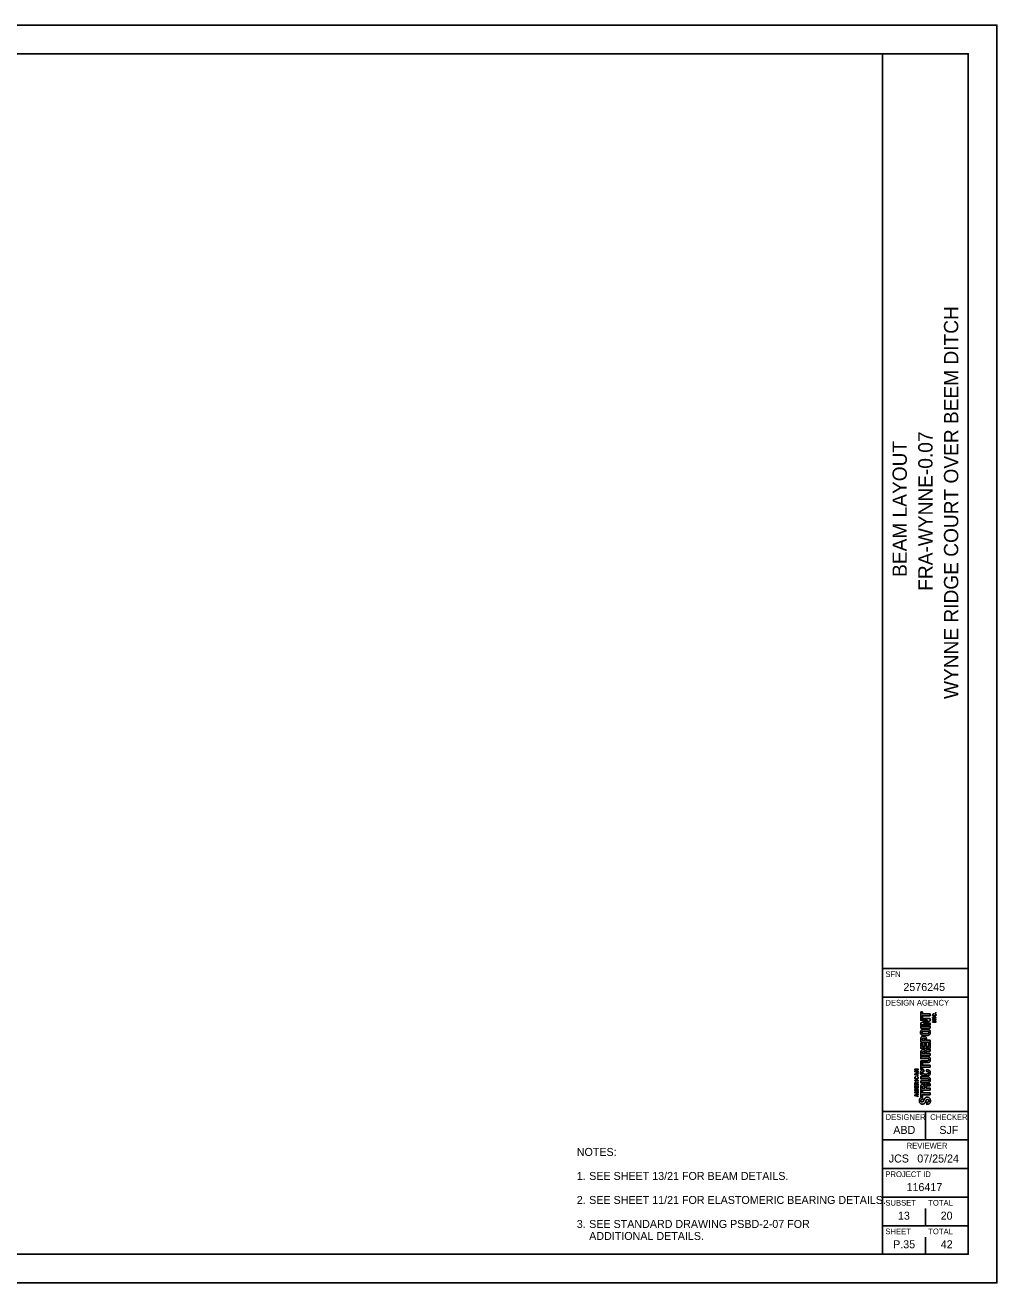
# Model space of a CAD drawing. Extents: x 0 to 34, y 0 to 22.
# Drawn here: x 17 to 34, y 0 to 22 of the extents above; entities that cross this region are included whole.
import ezdxf

# ---------------------------------------------------------------- set-up
doc = ezdxf.new("R2010")
doc.units = 0
for name, color, linetype in [('GE_X_Alignment', 7, 'Continuous'), ('PF_P_Grade_Line', 7, 'Continuous'), ('RW_X_CL', 7, 'Continuous'), ('RW_X_CL_20', 7, 'Continuous')]:
    doc.layers.add(name, color=color, linetype=linetype)

msp = doc.modelspace()

# ---------------------------------------------------------------- linework, layer by layer
at = {"layer": 'GE_X_Alignment'}
for p, q in [((32.75, 4), (32.75, 4)), ((32.75, 4), (32.75, 4)), ((32.75, 1), (32.75, 1.3)), ((32.375, 0.675), (32.375, 0.675)), ((32.75, 0.5), (32.75, 0.8))]:
    msp.add_line(p, q, dxfattribs=at)
for points in [[(32.67, 4.739), (32.697, 4.739), (32.697, 4.704), (32.833, 4.704), (32.833, 4.671), (32.697, 4.671), (32.697, 4.635), (32.67, 4.635), (32.67, 4.739)], [(32.67, 4.551), (32.781, 4.591), (32.781, 4.592), (32.67, 4.592), (32.67, 4.622), (32.833, 4.622), (32.833, 4.584), (32.719, 4.544), (32.719, 4.544), (32.833, 4.544), (32.833, 4.513), (32.67, 4.513), (32.67, 4.551)], [(32.875, 4.596), (32.875, 4.605), (32.925, 4.634), (32.925, 4.634), (32.875, 4.634), (32.875, 4.639), (32.935, 4.639), (32.935, 4.634), (32.88, 4.602), (32.88, 4.601), (32.935, 4.601), (32.935, 4.596), (32.875, 4.596)], [(32.935, 4.718), (32.927, 4.718), (32.927, 4.725), (32.935, 4.725), (32.935, 4.718)], [(32.833, 4.457), (32.67, 4.457), (32.67, 4.49), (32.833, 4.49), (32.833, 4.457)], [(32.875, 4.561), (32.875, 4.567), (32.935, 4.567), (32.935, 4.561), (32.875, 4.561)], [(32.833, 4.212), (32.67, 4.212), (32.67, 4.269)], [(32.67, 4.194), (32.697, 4.194), (32.697, 4.135), (32.735, 4.135), (32.735, 4.19), (32.762, 4.19), (32.762, 4.135), (32.806, 4.135), (32.806, 4.196), (32.833, 4.196), (32.833, 4.103), (32.67, 4.103), (32.67, 4.194)], [(32.694, 4.244), (32.743, 4.244), (32.743, 4.259)], [(32.694, 4.258), (32.694, 4.244)], [(32.768, 4.262), (32.768, 4.244), (32.833, 4.244), (32.833, 4.212)], [(32.833, 3.976), (32.67, 3.976), (32.67, 4.037)], [(32.694, 4.025), (32.694, 4.009)], [(32.694, 4.009), (32.741, 4.009), (32.741, 4.023)], [(32.752, 4.054), (32.752, 4.054)], [(32.764, 4.027), (32.764, 4.009), (32.833, 4.009), (32.833, 3.976)], [(32.816, 4.048), (32.784, 4.047)], [(32.832, 4.087), (32.833, 4.087), (32.833, 4.052)], [(32.67, 3.841), (32.697, 3.841), (32.697, 3.805), (32.833, 3.805), (32.833, 3.773), (32.697, 3.773), (32.697, 3.737), (32.67, 3.737), (32.67, 3.841)], [(32.565, 3.694), (32.565, 3.703), (32.615, 3.731), (32.615, 3.731), (32.565, 3.731), (32.565, 3.737), (32.625, 3.737), (32.625, 3.731), (32.569, 3.699), (32.569, 3.699), (32.625, 3.699), (32.625, 3.694), (32.565, 3.694)], [(32.625, 3.625), (32.565, 3.644), (32.565, 3.652), (32.625, 3.671), (32.625, 3.665), (32.605, 3.659), (32.605, 3.637), (32.625, 3.631), (32.625, 3.625)], [(32.565, 3.534), (32.565, 3.539), (32.625, 3.539), (32.625, 3.534), (32.565, 3.534)], [(32.601, 3.638), (32.601, 3.658), (32.569, 3.648), (32.569, 3.648), (32.601, 3.638)], [(32.596, 3.492), (32.625, 3.506), (32.625, 3.5), (32.597, 3.487), (32.597, 3.471), (32.625, 3.471), (32.625, 3.466), (32.565, 3.466), (32.565, 3.486)], [(32.625, 3.407), (32.565, 3.407), (32.565, 3.441), (32.569, 3.441), (32.569, 3.413), (32.591, 3.413), (32.591, 3.433), (32.596, 3.433), (32.596, 3.413), (32.62, 3.413), (32.62, 3.443), (32.625, 3.443), (32.625, 3.407)], [(32.625, 3.326), (32.565, 3.326), (32.565, 3.336), (32.615, 3.352), (32.615, 3.353), (32.565, 3.369), (32.565, 3.379), (32.625, 3.379), (32.625, 3.373), (32.569, 3.373), (32.569, 3.373), (32.625, 3.355), (32.625, 3.35), (32.569, 3.332), (32.569, 3.332), (32.625, 3.332), (32.625, 3.326)], [(32.625, 3.258), (32.565, 3.277), (32.565, 3.285), (32.625, 3.304), (32.625, 3.298), (32.605, 3.292), (32.605, 3.269), (32.625, 3.263), (32.625, 3.258)], [(32.569, 3.471), (32.593, 3.471), (32.593, 3.486)], [(32.569, 3.486), (32.569, 3.471)], [(32.833, 3.373), (32.67, 3.373), (32.67, 3.434)], [(32.67, 3.36), (32.697, 3.36), (32.697, 3.324), (32.833, 3.324), (32.833, 3.291), (32.697, 3.291), (32.697, 3.256), (32.67, 3.256), (32.67, 3.36)], [(32.694, 3.422), (32.694, 3.406)], [(32.694, 3.406), (32.741, 3.406), (32.741, 3.42)], [(32.752, 3.451), (32.752, 3.451)], [(32.764, 3.424), (32.764, 3.406), (32.833, 3.406), (32.833, 3.373)], [(32.816, 3.444), (32.784, 3.444)], [(32.832, 3.484), (32.833, 3.484), (32.833, 3.449)], [(32.601, 3.271), (32.601, 3.291), (32.569, 3.281), (32.569, 3.281), (32.601, 3.271)]]:
    msp.add_lwpolyline(points, dxfattribs=at)
for points in [[(32.893, 4.701), (32.889, 4.699), (32.885, 4.697), (32.883, 4.695), (32.88, 4.693), (32.879, 4.69), (32.879, 4.686), (32.879, 4.683), (32.88, 4.681), (32.881, 4.678), (32.882, 4.676), (32.884, 4.675), (32.887, 4.673), (32.889, 4.672), (32.892, 4.671), (32.895, 4.67), (32.898, 4.669), (32.902, 4.669), (32.905, 4.669), (32.909, 4.669), (32.912, 4.669), (32.915, 4.67), (32.919, 4.671), (32.921, 4.672), (32.924, 4.673), (32.926, 4.675), (32.928, 4.676), (32.929, 4.679), (32.931, 4.681), (32.931, 4.684), (32.931, 4.687), (32.931, 4.689), (32.931, 4.691), (32.93, 4.693), (32.929, 4.694), (32.928, 4.696), (32.927, 4.697), (32.926, 4.698), (32.924, 4.699), (32.922, 4.7), (32.921, 4.7), (32.919, 4.701), (32.917, 4.702), (32.917, 4.702), (32.918, 4.707), (32.918, 4.707), (32.92, 4.706), (32.923, 4.705), (32.925, 4.704), (32.927, 4.703), (32.929, 4.702), (32.931, 4.7), (32.932, 4.699), (32.934, 4.697), (32.934, 4.695), (32.935, 4.692), (32.936, 4.69), (32.936, 4.687), (32.936, 4.683), (32.935, 4.68), (32.934, 4.677), (32.932, 4.674), (32.93, 4.672), (32.927, 4.67), (32.925, 4.668), (32.921, 4.666), (32.918, 4.665), (32.914, 4.664), (32.91, 4.664), (32.905, 4.664), (32.901, 4.664), (32.896, 4.664), (32.893, 4.665), (32.889, 4.666), (32.886, 4.668), (32.883, 4.67), (32.88, 4.672), (32.878, 4.674), (32.877, 4.677), (32.875, 4.68), (32.875, 4.683), (32.875, 4.687), (32.875, 4.689), (32.875, 4.692), (32.876, 4.694), (32.877, 4.696), (32.878, 4.698), (32.88, 4.699), (32.881, 4.701), (32.883, 4.702), (32.885, 4.703), (32.887, 4.704), (32.889, 4.705), (32.892, 4.706), (32.892, 4.706), (32.893, 4.701), (32.893, 4.701)], [(32.751, 4.326), (32.739, 4.326), (32.727, 4.326), (32.717, 4.328), (32.706, 4.329), (32.697, 4.331), (32.69, 4.335), (32.682, 4.339), (32.677, 4.345), (32.672, 4.352), (32.668, 4.359), (32.666, 4.369), (32.666, 4.382), (32.666, 4.394), (32.668, 4.404), (32.672, 4.411), (32.677, 4.418), (32.682, 4.424), (32.69, 4.428), (32.697, 4.432), (32.706, 4.434), (32.717, 4.436), (32.727, 4.437), (32.739, 4.437), (32.751, 4.437), (32.758, 4.437), (32.764, 4.437), (32.771, 4.437)], [(32.751, 4.359), (32.762, 4.359), (32.771, 4.359), (32.779, 4.359), (32.787, 4.36), (32.793, 4.361), (32.798, 4.363), (32.803, 4.364), (32.806, 4.367), (32.808, 4.37), (32.81, 4.373), (32.812, 4.377), (32.812, 4.382), (32.812, 4.386), (32.81, 4.39), (32.808, 4.393), (32.806, 4.396), (32.803, 4.399), (32.798, 4.4), (32.793, 4.402), (32.787, 4.403), (32.779, 4.404), (32.771, 4.404), (32.762, 4.404), (32.751, 4.404), (32.74, 4.404), (32.731, 4.404), (32.723, 4.404), (32.716, 4.403), (32.709, 4.402), (32.704, 4.4), (32.7, 4.399), (32.696, 4.396), (32.694, 4.393), (32.692, 4.39), (32.691, 4.386), (32.691, 4.382), (32.691, 4.377), (32.692, 4.373), (32.694, 4.37), (32.696, 4.367), (32.7, 4.364), (32.704, 4.363), (32.709, 4.361), (32.716, 4.36), (32.723, 4.359), (32.731, 4.359), (32.74, 4.359), (32.751, 4.359)], [(32.771, 4.437), (32.776, 4.436), (32.781, 4.436), (32.785, 4.436), (32.796, 4.434), (32.805, 4.432), (32.812, 4.428), (32.82, 4.424), (32.825, 4.418), (32.83, 4.411), (32.834, 4.404), (32.836, 4.394), (32.836, 4.382), (32.836, 4.369), (32.834, 4.359), (32.83, 4.352), (32.825, 4.345), (32.82, 4.339), (32.812, 4.335), (32.805, 4.331), (32.796, 4.329), (32.785, 4.328), (32.775, 4.326), (32.763, 4.326), (32.751, 4.326)], [(32.67, 4.269), (32.67, 4.277), (32.671, 4.284), (32.674, 4.29), (32.677, 4.296), (32.68, 4.3), (32.685, 4.304), (32.689, 4.307), (32.695, 4.31), (32.701, 4.312), (32.706, 4.313), (32.712, 4.314), (32.719, 4.314), (32.727, 4.314), (32.734, 4.313), (32.741, 4.31), (32.747, 4.308), (32.752, 4.304), (32.756, 4.3), (32.76, 4.295), (32.763, 4.29), (32.765, 4.283), (32.767, 4.277), (32.768, 4.27), (32.768, 4.262)], [(32.743, 4.259), (32.743, 4.266), (32.741, 4.271), (32.737, 4.275), (32.733, 4.279), (32.727, 4.281), (32.719, 4.281), (32.711, 4.281), (32.705, 4.279), (32.7, 4.276), (32.696, 4.272), (32.694, 4.266), (32.694, 4.258)], [(32.67, 4.037), (32.67, 4.051), (32.673, 4.062), (32.68, 4.069), (32.687, 4.077), (32.698, 4.081), (32.712, 4.081), (32.723, 4.081), (32.732, 4.079), (32.739, 4.074), (32.745, 4.07), (32.75, 4.063), (32.752, 4.054)], [(32.741, 4.023), (32.741, 4.031), (32.739, 4.037), (32.735, 4.042), (32.732, 4.046), (32.725, 4.048), (32.717, 4.048), (32.702, 4.048), (32.694, 4.04), (32.694, 4.025)], [(32.752, 4.054), (32.753, 4.059), (32.755, 4.064), (32.757, 4.067), (32.759, 4.071), (32.762, 4.073), (32.766, 4.075), (32.769, 4.077), (32.774, 4.078), (32.78, 4.079), (32.786, 4.08), (32.794, 4.08), (32.802, 4.08), (32.811, 4.08), (32.818, 4.081), (32.822, 4.082), (32.827, 4.082), (32.83, 4.084), (32.832, 4.087)], [(32.784, 4.047), (32.778, 4.046), (32.773, 4.045), (32.769, 4.042), (32.766, 4.039), (32.764, 4.034), (32.764, 4.027)], [(32.833, 4.052), (32.831, 4.05), (32.828, 4.049), (32.825, 4.049), (32.822, 4.048), (32.819, 4.048), (32.816, 4.048)], [(32.67, 3.885), (32.67, 3.885), (32.783, 3.885), (32.783, 3.885), (32.787, 3.885), (32.791, 3.885), (32.795, 3.886), (32.798, 3.887), (32.801, 3.888), (32.803, 3.889), (32.806, 3.89), (32.808, 3.892), (32.809, 3.895), (32.811, 3.897), (32.812, 3.901), (32.812, 3.904), (32.812, 3.908), (32.811, 3.911), (32.809, 3.914), (32.808, 3.917), (32.806, 3.918), (32.803, 3.92), (32.801, 3.921), (32.798, 3.922), (32.795, 3.923), (32.791, 3.923), (32.787, 3.924), (32.783, 3.924), (32.783, 3.924), (32.67, 3.924), (32.67, 3.924), (32.67, 3.924), (32.67, 3.957), (32.67, 3.957), (32.67, 3.957), (32.783, 3.957), (32.783, 3.957), (32.794, 3.957), (32.802, 3.955), (32.809, 3.952), (32.816, 3.949), (32.821, 3.945), (32.825, 3.941), (32.829, 3.936), (32.832, 3.93), (32.834, 3.924), (32.835, 3.918), (32.836, 3.911), (32.836, 3.904), (32.836, 3.898), (32.835, 3.891), (32.834, 3.885), (32.833, 3.879), (32.83, 3.873), (32.826, 3.868), (32.822, 3.863), (32.817, 3.86), (32.81, 3.857), (32.803, 3.854), (32.794, 3.852), (32.783, 3.852), (32.783, 3.852), (32.67, 3.852), (32.67, 3.852), (32.67, 3.852), (32.67, 3.885), (32.67, 3.885)], [(32.582, 3.601), (32.578, 3.6), (32.575, 3.598), (32.572, 3.595), (32.57, 3.593), (32.569, 3.59), (32.569, 3.586), (32.569, 3.583), (32.569, 3.581), (32.571, 3.579), (32.572, 3.577), (32.574, 3.575), (32.576, 3.574), (32.579, 3.572), (32.581, 3.571), (32.585, 3.57), (32.588, 3.57), (32.591, 3.569), (32.595, 3.569), (32.598, 3.569), (32.602, 3.57), (32.605, 3.57), (32.608, 3.571), (32.611, 3.572), (32.613, 3.574), (32.616, 3.575), (32.618, 3.577), (32.619, 3.579), (32.62, 3.581), (32.621, 3.584), (32.621, 3.587), (32.621, 3.589), (32.62, 3.591), (32.62, 3.593), (32.619, 3.595), (32.618, 3.596), (32.617, 3.597), (32.615, 3.598), (32.614, 3.599), (32.612, 3.6), (32.61, 3.601), (32.608, 3.602), (32.606, 3.602), (32.606, 3.602), (32.607, 3.607), (32.607, 3.607), (32.61, 3.607), (32.612, 3.606), (32.615, 3.605), (32.617, 3.604), (32.619, 3.602), (32.62, 3.601), (32.622, 3.599), (32.623, 3.597), (32.624, 3.595), (32.625, 3.593), (32.625, 3.59), (32.625, 3.587), (32.625, 3.583), (32.625, 3.58), (32.623, 3.577), (32.622, 3.574), (32.62, 3.572), (32.617, 3.57), (32.614, 3.568), (32.611, 3.567), (32.607, 3.566), (32.604, 3.565), (32.599, 3.564), (32.595, 3.564), (32.59, 3.564), (32.586, 3.565), (32.582, 3.566), (32.579, 3.567), (32.575, 3.568), (32.573, 3.57), (32.57, 3.572), (32.568, 3.574), (32.566, 3.577), (32.565, 3.58), (32.564, 3.583), (32.564, 3.587), (32.564, 3.59), (32.565, 3.592), (32.566, 3.594), (32.566, 3.596), (32.568, 3.598), (32.569, 3.599), (32.571, 3.601), (32.572, 3.602), (32.575, 3.603), (32.577, 3.604), (32.579, 3.605), (32.581, 3.606), (32.581, 3.606), (32.582, 3.601), (32.582, 3.601)], [(32.725, 3.693), (32.713, 3.693), (32.704, 3.692), (32.699, 3.689), (32.693, 3.686), (32.691, 3.681), (32.691, 3.674), (32.691, 3.67), (32.692, 3.666), (32.694, 3.663), (32.696, 3.661), (32.7, 3.659), (32.705, 3.657), (32.71, 3.656), (32.716, 3.655), (32.724, 3.654), (32.732, 3.653), (32.742, 3.653), (32.753, 3.653), (32.766, 3.653), (32.776, 3.653), (32.783, 3.654), (32.791, 3.655), (32.797, 3.656), (32.801, 3.658), (32.805, 3.66), (32.808, 3.662), (32.809, 3.665), (32.811, 3.668), (32.812, 3.671), (32.812, 3.674), (32.812, 3.677), (32.811, 3.68), (32.81, 3.682), (32.809, 3.685), (32.807, 3.687), (32.804, 3.689), (32.801, 3.691), (32.797, 3.692), (32.792, 3.693), (32.786, 3.694), (32.779, 3.695), (32.77, 3.695), (32.77, 3.695), (32.77, 3.728), (32.77, 3.728), (32.779, 3.728), (32.787, 3.727), (32.795, 3.726), (32.803, 3.724), (32.81, 3.722), (32.816, 3.718), (32.822, 3.714), (32.827, 3.709), (32.831, 3.702), (32.834, 3.696), (32.836, 3.687), (32.836, 3.676), (32.836, 3.663), (32.834, 3.654), (32.83, 3.646), (32.825, 3.639), (32.82, 3.633), (32.812, 3.629), (32.805, 3.626), (32.796, 3.623), (32.785, 3.622), (32.775, 3.621), (32.763, 3.62), (32.751, 3.62), (32.739, 3.62), (32.727, 3.621), (32.717, 3.622), (32.706, 3.623), (32.697, 3.626), (32.69, 3.629), (32.682, 3.633), (32.677, 3.639), (32.672, 3.646), (32.668, 3.654), (32.666, 3.663), (32.666, 3.676), (32.666, 3.688), (32.668, 3.697), (32.672, 3.704), (32.676, 3.71), (32.681, 3.715), (32.687, 3.719), (32.692, 3.722), (32.699, 3.724), (32.706, 3.725), (32.712, 3.726), (32.719, 3.726), (32.725, 3.726), (32.725, 3.726), (32.725, 3.693), (32.725, 3.693)], [(32.67, 3.532), (32.67, 3.532), (32.783, 3.532), (32.783, 3.532), (32.787, 3.532), (32.791, 3.533), (32.795, 3.533), (32.798, 3.534), (32.801, 3.535), (32.803, 3.536), (32.806, 3.538), (32.808, 3.54), (32.809, 3.542), (32.811, 3.545), (32.812, 3.548), (32.812, 3.552), (32.812, 3.556), (32.811, 3.559), (32.809, 3.561), (32.808, 3.564), (32.806, 3.566), (32.803, 3.567), (32.801, 3.569), (32.798, 3.57), (32.795, 3.57), (32.791, 3.571), (32.787, 3.571), (32.783, 3.571), (32.783, 3.571), (32.67, 3.571), (32.67, 3.571), (32.67, 3.571), (32.67, 3.604), (32.67, 3.604), (32.67, 3.604), (32.783, 3.604), (32.783, 3.604), (32.794, 3.604), (32.802, 3.602), (32.809, 3.6), (32.816, 3.597), (32.821, 3.593), (32.825, 3.588), (32.829, 3.583), (32.832, 3.577), (32.834, 3.571), (32.835, 3.565), (32.836, 3.558), (32.836, 3.552), (32.836, 3.545), (32.835, 3.539), (32.834, 3.532), (32.833, 3.526), (32.83, 3.521), (32.826, 3.516), (32.822, 3.511), (32.817, 3.507), (32.81, 3.504), (32.803, 3.501), (32.794, 3.5), (32.783, 3.5), (32.783, 3.5), (32.67, 3.5), (32.67, 3.5), (32.67, 3.5), (32.67, 3.532), (32.67, 3.532)], [(32.565, 3.486), (32.565, 3.492), (32.566, 3.496), (32.569, 3.499), (32.572, 3.503), (32.576, 3.504), (32.581, 3.504), (32.585, 3.504), (32.588, 3.503), (32.591, 3.501), (32.593, 3.499), (32.595, 3.496), (32.596, 3.492)], [(32.593, 3.486), (32.593, 3.49), (32.592, 3.493), (32.59, 3.495), (32.588, 3.497), (32.585, 3.499), (32.581, 3.499), (32.577, 3.499), (32.575, 3.498), (32.573, 3.495), (32.57, 3.493), (32.569, 3.49), (32.569, 3.486)], [(32.67, 3.434), (32.67, 3.448), (32.673, 3.458), (32.68, 3.466), (32.687, 3.474), (32.698, 3.478), (32.712, 3.478), (32.723, 3.478), (32.732, 3.475), (32.739, 3.471), (32.745, 3.467), (32.75, 3.46), (32.752, 3.451)], [(32.741, 3.42), (32.741, 3.428), (32.739, 3.434), (32.735, 3.438), (32.732, 3.443), (32.725, 3.445), (32.717, 3.445), (32.702, 3.445), (32.694, 3.437), (32.694, 3.422)], [(32.752, 3.451), (32.753, 3.456), (32.755, 3.461), (32.757, 3.464), (32.759, 3.467), (32.762, 3.47), (32.766, 3.472), (32.769, 3.474), (32.774, 3.475), (32.78, 3.476), (32.786, 3.476), (32.794, 3.477), (32.802, 3.477), (32.811, 3.477), (32.818, 3.478), (32.822, 3.478), (32.827, 3.479), (32.83, 3.481), (32.832, 3.484)], [(32.784, 3.444), (32.778, 3.443), (32.773, 3.442), (32.769, 3.439), (32.766, 3.436), (32.764, 3.431), (32.764, 3.424)], [(32.833, 3.449), (32.831, 3.447), (32.828, 3.446), (32.825, 3.445), (32.822, 3.445), (32.819, 3.445), (32.816, 3.444)], [(32.775, 3.161), (32.775, 3.161), (32.781, 3.161), (32.781, 3.161), (32.785, 3.161), (32.789, 3.162), (32.793, 3.162), (32.796, 3.163), (32.799, 3.164), (32.801, 3.166), (32.804, 3.168), (32.806, 3.171), (32.807, 3.174), (32.809, 3.177), (32.809, 3.181), (32.809, 3.186), (32.809, 3.192), (32.807, 3.197), (32.804, 3.201), (32.8, 3.206), (32.794, 3.208), (32.786, 3.208), (32.782, 3.208), (32.779, 3.208), (32.776, 3.207), (32.773, 3.205), (32.77, 3.204), (32.767, 3.201), (32.765, 3.198), (32.763, 3.195), (32.761, 3.191), (32.759, 3.187), (32.757, 3.181), (32.755, 3.175), (32.752, 3.167), (32.749, 3.16), (32.745, 3.154), (32.742, 3.147), (32.738, 3.142), (32.734, 3.138), (32.73, 3.134), (32.725, 3.131), (32.719, 3.129), (32.713, 3.128), (32.706, 3.127), (32.699, 3.127), (32.68, 3.127), (32.667, 3.132), (32.658, 3.142), (32.649, 3.152), (32.644, 3.166), (32.644, 3.184), (32.644, 3.192), (32.645, 3.2), (32.647, 3.207), (32.649, 3.214), (32.651, 3.22), (32.656, 3.225), (32.66, 3.23), (32.665, 3.234), (32.671, 3.237), (32.677, 3.24), (32.685, 3.241), (32.694, 3.241), (32.694, 3.241), (32.699, 3.241), (32.699, 3.241), (32.699, 3.241), (32.699, 3.205), (32.699, 3.205), (32.69, 3.205), (32.683, 3.204), (32.679, 3.201), (32.674, 3.197), (32.671, 3.192), (32.671, 3.185), (32.671, 3.181), (32.672, 3.178), (32.673, 3.175), (32.675, 3.172), (32.676, 3.17), (32.678, 3.168), (32.68, 3.167), (32.682, 3.165), (32.685, 3.165), (32.688, 3.164), (32.69, 3.164), (32.693, 3.164), (32.699, 3.164), (32.704, 3.165), (32.707, 3.168), (32.711, 3.17), (32.715, 3.175), (32.718, 3.183), (32.718, 3.183), (32.731, 3.212), (32.731, 3.212), (32.734, 3.219), (32.737, 3.225), (32.74, 3.229), (32.744, 3.234), (32.747, 3.237), (32.751, 3.24), (32.755, 3.243), (32.76, 3.245), (32.764, 3.246), (32.769, 3.247), (32.774, 3.247), (32.78, 3.247), (32.799, 3.247), (32.814, 3.242), (32.823, 3.23), (32.832, 3.219), (32.837, 3.203), (32.837, 3.183), (32.837, 3.162), (32.832, 3.147), (32.823, 3.138), (32.813, 3.128), (32.8, 3.124), (32.783, 3.124), (32.783, 3.124), (32.775, 3.124), (32.775, 3.124), (32.775, 3.124), (32.775, 3.161), (32.775, 3.161)]]:
    msp.add_open_spline(points, degree=3, dxfattribs=at)
at = {"layer": 'RW_X_CL'}
for p, q in [((32, 0.5), (32, 21.5)), ((32, 5.5), (33.5, 5.5)), ((32, 5), (33.5, 5)), ((32, 3), (33.5, 3)), ((32.75, 3), (32.75, 2.5)), ((32, 2.5), (33.5, 2.5)), ((32, 2), (33.5, 2)), ((32, 1.5), (33.5, 1.5)), ((32, 1), (33.5, 1))]:
    msp.add_line(p, q, dxfattribs=at)
msp.add_lwpolyline([(1.5, 21.5), (33.5, 21.5), (33.5, 0.5), (1.5, 0.5)], close=True, dxfattribs=at)
at = {"layer": 'RW_X_CL_20'}
msp.add_lwpolyline([(0, 0), (34, 0), (34, 22), (0, 22)], close=True, dxfattribs=at)

# ---------------------------------------------------------------- texts
at = {"layer": 'GE_X_Alignment'}
for s, p in [('WYNNE RIDGE COURT OVER BEEM DITCH', (33.325, 10.212)), ('FRA-WYNNE-0.07', (32.875, 12.106)), ('BEAM LAYOUT', (32.425, 12.349))]:
    msp.add_text(s, height=0.25, rotation=90, dxfattribs=at).set_placement(p)
for s, height, p in [('SFN', 0.1, (32.05, 5.35)), ('2576245', 0.14, (32.365, 5.105)), ('DESIGN AGENCY', 0.1, (32.05, 4.85)), ('DESIGNER', 0.1, (32.054, 2.85)), ('CHECKER', 0.1, (32.835, 2.85)), ('ABD', 0.14, (32.188, 2.605)), ('SJF', 0.14, (32.994, 2.605)), ('REVIEWER', 0.1, (32.422, 2.35)), ('JCS', 0.14, (32.109, 2.105)), ('07/25/24', 0.14, (32.608, 2.105)), ('PROJECT ID', 0.1, (32.05, 1.85)), ('116417', 0.14, (32.42, 1.605)), ('SUBSET', 0.1, (32.05, 1.35)), ('TOTAL', 0.1, (32.8, 1.35)), ('13', 0.14, (32.27, 1.105)), ('20', 0.14, (33.017, 1.105)), ('SHEET', 0.1, (32.05, 0.85)), ('TOTAL', 0.1, (32.8, 0.85)), ('P.35', 0.14, (32.185, 0.605)), ('42', 0.14, (33.019, 0.605))]:
    msp.add_text(s, height=height, dxfattribs=at).set_placement(p)
at = {"layer": 'PF_P_Grade_Line'}
for s, p in [('NOTES:', (26.651, 2.22)), ('1.', (26.651, 1.8)), ('SEE SHEET 13/21 FOR BEAM DETAILS.', (26.868, 1.8)), ('2.', (26.651, 1.38)), ('SEE SHEET 11/21 FOR ELASTOMERIC BEARING DETAILS.', (26.868, 1.38)), ('3.', (26.651, 0.96)), ('SEE STANDARD DRAWING PSBD-2-07 FOR', (26.868, 0.96)), ('ADDITIONAL DETAILS.', (26.868, 0.75))]:
    msp.add_text(s, height=0.14, dxfattribs=at).set_placement(p)

doc.saveas('drawing.dxf')
